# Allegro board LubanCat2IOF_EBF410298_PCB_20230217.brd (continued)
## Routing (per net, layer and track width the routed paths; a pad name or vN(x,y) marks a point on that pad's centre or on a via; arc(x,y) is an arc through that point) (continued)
I2C0_SDA: length 46.9
  TOP w0.173: v1(18.84,64.74) 19.14,64.44 41.15,64.44 41.6,63.98 J38.109
  ART03 w0.16: v1(18.84,64.74) 17.91,65.67 17.91,69.11 15.75,71.27 15.75,82.06 v1(14.1,83.71)
  BOTTOM w0.173: U17.5 v1(14.1,83.71)
I2C1_SCL: length 187.9
  TOP w0.173: J38.115 43.1,59.3 R35.2 42.8,58.33 42.8,38.58 v1(42.95,38.42) ; J23.9 155.8,68.43 156.14,68.08 156.14,53.13 155.75,52.74 v1(154.54,52.74) 154.05,52.24 154.05,49.35 156.21,47.19 156.21,36.45 155.78,36.01 146.94,36.01 v1(146.71,36.24)
  BOTTOM w0.173: v1(154.54,52.74) 154.12,52.74 153.07,53.78 J22.6 ; v1(42.95,38.42) 43.41,37.96 103.83,37.96 104.65,38.78 119.35,38.78 122.05,36.09 128.85,36.09 133.22,31.72 145.69,31.72 146.71,32.74 v1(146.71,36.24)
I2C1_SDA: length 195.5
  TOP w0.173: v1(42.44,37.64) 42.45,37.64 42.45,58.43 R33.2 42.6,59.66 J38.113 ; v1(145.71,36.24) 146.37,35.58 156.14,35.58 156.7,36.15 156.7,47.39 154.54,49.55 v1(154.54,51.74) 156.25,51.74 156.64,52.13 156.64,68.29 156,68.93 J23.10
  BOTTOM w0.173: v1(154.54,51.74) 153,53.28 J22.5 ; v1(145.71,36.24) 146.2,36.73 146.96,36.73 147.31,36.39 147.31,32.55 145.92,31.16 133.07,31.16 128.62,35.61 121.82,35.61 119.07,38.35 104.98,38.35 104.14,37.51 42.57,37.51 v1(42.44,37.64)
I2C5_SCL_M0: length 194
  TOP w0.173: v1(95.6,60.91) 95.6,60.9 95.07,60.37 94.27,60.37 94.1,60.54 J38.313 ; v1(153.85,46.22) 153.32,45.69 J26.9
  ART03 w0.16: v1(95.6,60.91) 96.13,60.37 109.7,60.37 112.27,57.81 112.27,43.71 114.55,41.42 114.55,25.75 113.72,24.91 113.72,23.24 113.03,22.55 113.03,16.29 112.71,15.97 107.19,15.97 106.95,15.73 J28.4 106.95,10.93 107.27,10.61 142.85,10.61 145.29,13.05 154.7,13.05 155.02,13.37 155.02,34.62 153.85,35.79 v1(153.85,46.22)
  BOTTOM w0.173: v1(153.85,46.22) 153.85,47.61 154.19,47.95 155.62,47.95 156.67,49 156.67,70.33 155.02,71.98 J24.6 ; R147.2 95.64,60.94 v1(95.6,60.91)
I2C5_SDA_M0: length 197.6
  TOP w0.173: J26.10 152.82,46.19 v1(152.85,46.22) ; J38.314 v1(94.6,60.91)
  ART03 w0.16: v1(94.6,60.91) 95.57,59.94 109.12,59.94 111.84,57.22 111.84,43.53 114.12,41.25 114.12,25.93 113.28,25.09 113.28,23.41 112.6,22.73 112.6,17.14 112.09,16.63 105.27,16.63 104.95,16.31 J28.5 104.95,10.5 105.27,10.18 143.03,10.18 145.47,12.62 155.11,12.62 155.55,13.06 155.55,34.84 154.38,36.01 154.38,46.37 154.05,46.7 153.33,46.7 v1(152.85,46.22)
  BOTTOM w0.173: v1(94.6,60.91) 94.48,61.03 R146.2 ; J24.5 154.75,71.48 156.29,69.95 156.29,49.16 155.46,48.33 153.16,48.33 152.85,48.02 v1(152.85,46.22)
LCD0_BL_PWM: length 102.2
  TOP w0.173: J38.187 v1(62.6,60.91) ; J23.13 v1(153.96,70.43)
  ART03 w0.16: v1(133.45,69.72) 133.94,70.21 147.79,70.21 148.18,69.82 153.36,69.82 v1(153.96,70.43)
  BOTTOM w0.173: v1(62.6,60.91) 63.11,60.4 65.33,60.4 74.17,69.24 96.88,69.24 99.47,66.64 103.37,66.64 104.5,67.76 114.2,67.76 115.06,68.63 132.35,68.63 v1(133.45,69.72)
LCD0_PWR_EN: length 109.7
  TOP w0.173: J38.235 74.6,60.41 v1(75.1,59.91) ; R195.1 v1(140.6,61.9)
  ART03 w0.16: v1(75.1,59.91) 75.61,60.42 77.27,60.42 78.3,59.39 90.72,59.39 92.25,57.86 107.04,57.86 108.28,56.61 108.28,45.77 107.65,45.13 107.65,41.39 v1(108.84,40.19)
  BOTTOM w0.173: v1(108.84,40.19) 108.88,40.15 132.89,40.15 134.85,42.11 138.11,42.11 138.46,42.45 138.46,45.54 138.81,45.89 141.69,45.89 142.04,46.24 142.04,60.46 v1(140.6,61.9)
LCD1_BL_PWM: length 118.4
  TOP w0.173: J38.185 62.1,58.41 v1(62.6,57.91) ; J26.13 v1(149.43,47.69)
  BOTTOM w0.173: v1(62.6,57.91) 63.19,58.49 65.89,58.49 73.41,66.01 92.79,66.01 94.62,67.84 96.24,67.84 98.48,65.6 102.49,65.6 103.1,64.99 118.34,64.99 120.52,67.17 141.99,67.17 142.52,66.65 142.52,48.7 142.86,48.36 148.77,48.36 v1(149.43,47.69)
LCD1_PWR_EN: length 87.5
  TOP w0.173: R200.2 139.83,39.04 139.6,39.26 134.75,39.26 v1(134.21,39.8) ; J38.237 v1(75.1,60.91)
  ART03 w0.16: v1(107.84,40.19) 106.98,41.05 106.98,45.64 107.67,46.33 107.67,56.25 106.56,57.36 92.22,57.36 90.58,59 77.83,59 77.43,59.39 74.93,59.39 74.91,59.42 74.9,59.42 74.61,59.7 74.61,60.42 v1(75.1,60.91)
  BOTTOM w0.173: v1(134.21,39.8) 134.06,39.65 108.39,39.65 v1(107.84,40.19)
LED_USR: length 111.2
  TOP w0.173: LED2.2 v1(139.07,98.39) ; v1(57.85,67.85) 58.35,68.35 J38.168
  BOTTOM w0.173: v1(57.85,67.85) 58.24,68.24 62.63,68.24 64.31,69.92 64.31,78.25 64.89,78.83 93.77,78.83 95.3,80.36 95.3,81.1 95.78,81.58 114.68,81.58 115.03,81.93 134.66,81.93 135,82.28 135,87.55 135.56,88.11 135.56,95.96 136.42,96.82 138.83,96.82 139.07,97.07 v1(139.07,98.39)
M2PCIE_3V3: length 53
  TOP w0.305: U21.1 v1(142.49,79.17) ; J17.14 139.9,83.6 v1(139.66,83.36) 139.4,83.62 J17.12 ; C69.2 R73.2 v1(135.13,57.59) ; v1(139.95,71.72) 140,71.67 R83.1 ; J17.18 140.9,83.6 v1(140.66,83.36) 140.4,83.62 J17.16 ; v1(139.45,80.82) 138.74,80.82 138.44,80.51 R86.1 R85.1 ; J17.4 137.4,83.6 v1(137.16,83.36) 136.9,83.62 J17.2 ; J17.70 153.9,85.87 v1(154.18,86.15) 154.4,85.93 J17.72
  TOP w0.381: v1(154.18,86.15) v1(154.18,87.15)
  ART04 w0.305: v1(135.13,57.59) 136.55,57.59 136.86,57.89 136.86,68.8
  BOTTOM w0.305: v1(139.95,71.72) 140,71.67 R83.1 ; R81.2 139.18,86.91 v1(138.94,87.15) ; v1(139.66,83.36) 139.44,83.14 C116.1 C115.1 142.16,78.15 142.49,78.48 v1(142.49,79.17) 145.61,79.17 146,78.79 R145.2 C136.1
  BOTTOM w0.381: v1(152.15,86.79) C130.1 C131.1 C129.1
  vias: v1(136.95,69.72) v1(137.95,69.72) v1(138.95,69.72) v1(138.95,68.72) v1(139.94,87.15) v1(152.15,85.79)
M2PCIE_PWR_EN: length 113.5
  TOP w0.173: v1(47.54,55.45) 47.6,55.51 J38.133 ; v1(126.11,52.5) v1(126.11,50.97)
  BOTTOM w0.173: v1(126.11,52.5) 132.29,52.5 132.64,52.84 132.64,61 132.87,61.24 136.13,61.24 R76.2 ; v1(47.54,55.45) 47.05,54.96 47.05,53.1 47.35,52.8 63.93,52.8 64.54,53.41 71.78,53.41 72.06,53.13 72.06,51.56 72.41,51.21 79.05,51.21 80.25,52.41 92.24,52.41 93.12,53.29 111.23,53.29 113.54,50.97 v1(126.11,50.97)
MDIN0_PHY0: length 36
  TOP w0.114: U18.2 68.71,51.65 68.79,51.73 68.79,52.03 69.18,52.42 69.18,52.55 v1(68.83,52.91)
  ART04 w0.102: v1(68.83,52.91) 69.27,53.35 69.27,76.75 73.91,81.39 73.91,82.8 73.76,82.95 72.95,82.95 72.84,82.85 J11.3
MDIN0_PHY1: length 35.3
  TOP w0.114: v1(89.4,52.91) 89.69,52.62 89.69,52.41 89.27,51.99 89.27,51.76 89.16,51.65 U19.2
  ART04 w0.102: v1(89.4,52.91) 89.58,53.08 89.58,53.09 89.72,53.23 89.72,78.66 92.23,81.16 92.23,82.93 92.1,83.05 91.23,83.05 91.1,82.93 J18.3
MDIN1_PHY0: length 43.3
  TOP w0.114: v1(67.68,53.93) 68.03,53.58 68.03,52.75 67.59,52.31 67.59,51.73 67.51,51.65 U18.5
  ART04 w0.102: v1(67.68,53.93) 68.02,54.27 68.02,77.49 71.31,80.77 71.31,82.78 70.18,83.9 70.18,85.85 69.98,86.05 67.97,86.05 67.76,85.85 J11.7
MDIN1_PHY1: length 43.1
  TOP w0.114: v1(88.11,53.93) 88.48,53.55 88.48,52.75 88.04,52.31 88.04,51.73 87.96,51.65 U19.5
  ART04 w0.102: v1(88.11,53.93) 88.42,54.24 88.42,79.66 89.69,80.93 89.69,83.28 89.48,83.49 88.71,83.49 88.34,83.85 88.34,85.96 88.2,86.1 86.18,86.1 86.02,85.94 J18.7
MDIN2_PHY0: length 34.9
  TOP w0.114: U18.7 66.71,51.65 66.79,51.73 66.79,52.58 v1(66.46,52.91)
  ART04 w0.102: J11.6 68.78,84.5 68.78,80.38 66.78,78.37 66.78,54.9 66.78,53.22 v1(66.46,52.91)
MDIN2_PHY1: length 34
  TOP w0.114: U19.7 87.16,51.65 87.24,51.73 87.24,52.58 v1(86.91,52.91)
  ART04 w0.102: v1(86.91,52.91) 87.22,53.22 87.22,54.9 87.22,84.68 J18.6
MDIN3_PHY0: length 34.3
  TOP w0.114: U18.10 65.51,51.65 65.59,51.73 65.59,53.62 v1(65.26,53.95)
  ART04 w0.102: J11.9 65.22,82.82 65.43,83.02 66.15,83.02 66.35,82.82 66.35,80.38 65.57,79.6 65.57,54.25 v1(65.26,53.95)
MDIN3_PHY1: length 34.7
  TOP w0.114: v1(85.71,53.95) 86.04,53.62 86.04,51.73 85.96,51.65 U19.10
  ART04 w0.102: v1(85.71,53.95) 86.02,54.25 86.02,79.83 84.66,81.19 84.66,82.88 84.48,83.05 83.66,83.05 83.48,82.88 J18.9
MDIP0_PHY0: length 36
  TOP w0.114: v1(69.72,52.91) 69.42,52.61 69.42,52.32 69.03,51.93 69.03,51.73 69.11,51.65 U18.1
  ART04 w0.102: J11.2 74.19,84.67 74.19,81.28 69.55,76.63 69.55,53.07 v1(69.72,52.91)
MDIP0_PHY1: length 35.2
  TOP w0.114: U19.1 89.56,51.65 89.52,51.69 89.52,51.89 89.93,52.31 89.93,52.54 v1(90.29,52.91)
  ART04 w0.102: v1(90.29,52.91) 90,53.2 90,78.54 92.51,81.05 92.51,84.62 J18.2
MDIP1_PHY0: length 43.4
  TOP w0.114: U18.4 67.91,51.65 67.83,51.73 67.83,52.21 68.28,52.65 68.28,53.63 v1(68.57,53.93)
  ART04 w0.102: J11.4 71.57,84.06 71.78,83.86 72.57,83.86 72.67,83.96 72.67,85.98 72.57,86.08 70.56,86.08 70.46,85.98 70.46,84.02 71.59,82.89 71.59,80.66 68.3,77.37 68.3,54.2 v1(68.57,53.93)
MDIP1_PHY1: length 43.2
  TOP w0.114: v1(89,53.93) 88.72,53.66 88.72,52.65 88.28,52.21 88.28,51.73 88.36,51.65 U19.4
  ART04 w0.102: J18.4 89.83,86.81 89.73,86.91 87.54,86.91 87.44,86.81 87.44,86.48 87.54,86.38 88.32,86.38 88.62,86.08 88.62,83.97 88.82,83.77 89.6,83.77 89.97,83.4 89.97,80.82 88.7,79.55 88.7,54.23 v1(89,53.93)
MDIP2_PHY0: length 34.8
  TOP w0.114: v1(67.36,52.91) 67.03,52.58 67.03,51.73 67.11,51.65 U18.6
  ART04 w0.102: J11.5 70.3,82.8 70.15,82.96 69.24,82.96 69.06,82.77 69.06,80.26 67.06,78.25 67.06,53.2 v1(67.36,52.91)
MDIP2_PHY1: length 34.1
  TOP w0.114: v1(87.8,52.91) 87.48,52.58 87.48,51.73 87.56,51.65 U19.6
  ART04 w0.102: J18.5 88.56,82.93 88.34,83.16 87.73,83.16 87.5,82.93 87.5,53.2 v1(87.8,52.91)
MDIP3_PHY0: length 34.4
  TOP w0.114: v1(66.16,53.95) 65.83,53.62 65.83,51.73 65.91,51.65 U18.9
  ART04 w0.102: v1(66.16,53.95) 65.85,54.25 65.85,79.49 66.63,80.27 66.63,84.61 J11.8
MDIP3_PHY1: length 34.6
  TOP w0.114: U19.9 86.36,51.65 86.28,51.73 86.28,53.62 v1(86.6,53.95)
  ART04 w0.102: J18.8 84.94,84.57 84.94,81.3 86.3,79.94 86.3,54.25 v1(86.6,53.95)
MIC1_INN: length 50.4
  TOP w0.114: v1(23.35,67.74) 22.85,68.24 J38.34
  BOTTOM w0.114: 44.2,78.6 J30.1 ; 44.2,78.6 43.98,78.38 43.98,76.59 44.2,76.37 ; 44.2,78.6 43.97,78.83 43.97,80.6 D30.1 44.02,81.75 44.03,81.76 44.03,83.03 44.25,83.24 45.78,83.24 46.15,83.61 46.15,88.35 J27.3 43.9,90.6 J27.4 ; 44.2,76.37 44.2,76.37 43.97,76.15 43.97,74.75 41.63,72.41 24.66,72.41 23.88,71.62 23.88,68.26 v1(23.35,67.74) ; 44.2,76.37 C217.2 R215.1
MIC1_INP: length 60.7
  TOP w0.114: J27.2 41.97,94.3 41.74,94.07 41.74,85.23 41.97,85 J27.1 ; J38.36 v1(23.35,68.74)
  BOTTOM w0.114: 43.5,78.6 J30.2 ; 43.5,78.6 43.74,78.36 43.74,76.61 43.5,76.37 43.5,76.37 ; 43.5,78.6 43.73,78.83 43.73,80.6 D29.1 43.79,81.86 43.79,83.13 44.15,83.49 45.68,83.49 45.91,83.71 45.91,86.03 45.68,86.25 44.03,86.25 43.8,86.03 J27.1 ; 43.5,76.37 C217.1 R214.2 ; 43.5,76.37 43.73,76.15 43.73,74.85 41.53,72.65 24.56,72.65 23.63,71.72 23.63,69.02 v1(23.35,68.74)
MINIPCIE_3V3: length 29.3
  TOP w0.305: J35.39 v1(110.3,75.31) ; v1(128.26,70.54) 128.3,70.5 J35.2 ; J35.24 v1(116.3,66.85) ; J35.52 v1(105.1,66.85) ; v1(132.13,59.59) 131.75,59.97 119.57,59.97 119.26,60.27 C32.1 R14.1 ; J35.41 v1(109.5,75.31)
  BOTTOM w0.305: v1(110.3,75.31) 110.24,75.36 C58.1 ; C55.1 105.16,66.78 v1(105.1,66.85) ; v1(116.3,66.85) 116.93,67.48 C56.1 ; R22.1 v1(128.26,70.54) 128.27,70.53 C57.1 ; v1(132.13,59.59) v1(132.13,61.73)
  vias: v1(132.13,64.73) v1(132.13,63.73) v1(132.13,62.73)
MINIPCIE_NWDISABLE: length 47.3
  TOP w0.173: R62.2 v1(117.98,63.83) ; J38.243 76.6,60.41 v1(77.1,59.91)
  BOTTOM w0.173: v1(77.1,59.91) 77.61,60.41 77.61,61.11 78.01,61.51 82.96,61.51 84.48,63.04 96.57,63.04 97.45,62.16 114.26,62.16 115.42,63.32 117.48,63.32 v1(117.98,63.83)
MINIPCIE_PWR_EN: length 85.5
  TOP w0.173: J38.245 v1(77.1,60.91)
  ART03 w0.16: v1(77.1,60.91) 77.24,60.91 78.36,59.79 90.98,59.79 92.44,58.33 107.43,58.33 108.74,57.02 108.74,45.06 v1(108.34,44.66)
  ART04 w0.16: v1(122.86,65.68) 122.86,61.41 122.22,60.78 122.22,51.65 121.9,51.33 119.78,51.33 119.46,51.01 119.46,45.27 120.03,44.7 v1(120.03,44.66)
  BOTTOM w0.173: R16.1 122.81,65.63 v1(122.86,65.68) ; v1(108.34,44.66) v1(120.03,44.66)
MIPI_CSI_RX_CLK0N: length 115.7
  TOP w0.114: J38.240 76.35,71.5 76.42,71.57 arc(76.46,71.64) 76.48,71.71 76.48,72.38 arc(76.44,72.59) 76.32,72.76 v1(76.15,72.93)
  ART03 w0.102: v1(155.52,55.74) 155.36,55.58 arc(155.2,55.48) 155.01,55.44 153.94,55.44 arc(153.85,55.48) 153.81,55.57 arc(153.78,55.66) 153.68,55.7 153.44,55.7 arc(153.34,55.66) 153.31,55.57 arc(153.27,55.48) 153.18,55.44 152.93,55.44 arc(152.84,55.48) 152.8,55.57 arc(152.76,55.66) 152.67,55.7 152.42,55.7 arc(152.33,55.66) 152.29,55.57 arc(152.25,55.48) 152.16,55.44 148.74,55.44 arc(147.95,55.77) 147.62,56.56 147.62,60 arc(147.59,60.19) 147.48,60.36 145.77,62.06 arc(144.69,62.78) 143.41,63.04 139.16,63.04 arc(138.31,63.21) 137.59,63.69 arc(136.57,64.37) 135.36,64.61 134.23,64.61 arc(133.77,64.71) 133.38,64.97 133.32,65.02 arc(132.62,65.49) 131.8,65.66 130.89,65.66 arc(129.88,65.86) 129.02,66.43 127.15,68.3 arc(126.56,68.69) 125.86,68.83 105.03,68.83 arc(104.19,68.66) 103.48,68.19 arc(103.45,68.15) 103.41,68.11 arc(102.54,67.57) 101.54,67.38 99.39,67.38 arc(99.25,67.44) 99.19,67.59 99.19,68.2 arc(99.01,68.63) 98.58,68.8 94.46,68.8 arc(94,68.61) 93.8,68.14 93.8,65.99 arc(93.68,65.7) 93.39,65.58 73.35,65.58 arc(73.05,65.64) 72.8,65.81 arc(72.63,66.06) 72.57,66.36 72.57,67.98 arc(72.61,68.09) 72.72,68.13 arc(72.83,68.17) 72.87,68.28 72.87,68.49 arc(72.83,68.59) 72.72,68.64 arc(72.61,68.68) 72.57,68.79 72.57,68.99 arc(72.61,69.1) 72.72,69.15 arc(72.83,69.19) 72.87,69.3 72.87,69.5 arc(72.83,69.61) 72.72,69.65 arc(72.61,69.7) 72.57,69.81 72.57,70.04 arc(72.61,70.14) 72.72,70.19 arc(72.83,70.23) 72.87,70.34 72.87,70.44 arc(72.83,70.55) 72.72,70.59 arc(72.61,70.64) 72.57,70.75 72.57,70.85 arc(72.61,70.96) 72.72,71 arc(72.83,71.04) 72.87,71.15 72.87,71.25 arc(72.83,71.36) 72.72,71.41 arc(72.61,71.45) 72.57,71.56 72.57,73.04 arc(72.77,73.52) 73.25,73.72 76.26,73.72 arc(76.4,73.66) 76.46,73.52 76.46,73.44 arc(76.42,73.25) 76.31,73.09 v1(76.15,72.93)
  BOTTOM w0.114: J22.10 152.15,55.78 arc(152.22,55.77) 152.29,55.72 152.3,55.71 arc(152.37,55.67) 152.44,55.65 153.66,55.65 arc(153.81,55.62) 153.93,55.54 154.01,55.46 arc(154.06,55.43) 154.11,55.42 154.98,55.42 arc(155.18,55.46) 155.35,55.57 v1(155.52,55.74)
MIPI_CSI_RX_CLK0P: length 115
  TOP w0.114: J38.242 76.85,71.42 arc(76.84,71.49) 76.79,71.56 76.78,71.57 arc(76.74,71.64) 76.72,71.71 76.72,72.38 arc(76.76,72.59) 76.87,72.76 v1(77.05,72.93)
  ART03 w0.102: v1(155.52,54.85) 155.36,55.01 arc(155.2,55.12) 155.01,55.16 148.74,55.16 arc(147.75,55.57) 147.35,56.56 147.35,60 arc(147.33,60.09) 147.28,60.16 145.58,61.86 arc(144.58,62.53) 143.41,62.76 139.16,62.76 arc(138.2,62.95) 137.39,63.49 arc(136.46,64.12) 135.36,64.33 134.23,64.33 arc(133.66,64.45) 133.18,64.77 133.12,64.83 arc(132.51,65.23) 131.8,65.38 130.89,65.38 arc(129.77,65.6) 128.82,66.23 126.96,68.1 arc(126.45,68.43) 125.86,68.55 105.03,68.55 arc(104.3,68.41) 103.68,67.99 103.6,67.91 103.6,67.91 arc(102.64,67.31) 101.54,67.1 99.39,67.1 arc(99.05,67.24) 98.91,67.59 98.91,68.2 arc(98.81,68.43) 98.58,68.53 94.46,68.53 arc(94.19,68.41) 94.08,68.14 94.08,65.99 arc(93.88,65.5) 93.39,65.3 73.35,65.3 arc(72.94,65.38) 72.6,65.61 arc(72.37,65.95) 72.29,66.36 72.29,73.04 arc(72.57,73.72) 73.25,74 76.26,74 arc(76.6,73.86) 76.74,73.52 76.74,73.44 arc(76.78,73.25) 76.89,73.09 v1(77.05,72.93)
  BOTTOM w0.114: J22.9 152.15,55.28 arc(152.22,55.3) 152.29,55.34 152.3,55.35 arc(152.37,55.4) 152.44,55.41 153.66,55.41 arc(153.71,55.4) 153.76,55.37 153.84,55.29 arc(153.96,55.21) 154.11,55.18 154.98,55.18 arc(155.18,55.14) 155.35,55.02 v1(155.52,54.85)
MIPI_CSI_RX_CLK1N: length 115.5
  TOP w0.114: v1(77.15,67.77) 77.41,68.03 arc(77.46,68.11) 77.48,68.19 77.48,69.02 arc(77.47,69.07) 77.44,69.11 77.41,69.13 arc(77.37,69.21) 77.35,69.29 J38.244
  ART03 w0.102: v1(77.15,67.77) 77.31,67.93 arc(77.42,68.09) 77.46,68.29 77.46,69.03 arc(77.4,69.18) 77.26,69.24 75.64,69.24 arc(75.3,69.38) 75.16,69.72 75.16,70.67 arc(75.34,71.11) 75.78,71.29 78.07,71.29 arc(78.45,71.14) 78.6,70.76 78.6,70.03 arc(78.86,69.77) 79.11,70.03 79.11,70.76 arc(79.27,71.14) 79.64,71.29 81.46,71.29 arc(81.6,71.35) 81.66,71.5 81.66,72.66 arc(82.14,73.14) 82.63,72.66 82.63,71.5 arc(82.69,71.35) 82.83,71.29 84.75,71.29 arc(84.97,71.39) 85.06,71.61 85.06,72.26 arc(85.21,72.6) 85.55,72.74 85.78,72.74 arc(86.12,72.6) 86.26,72.26 86.26,71.39 arc(86.46,71.18) 86.66,71.39 86.66,72.26 arc(86.81,72.6) 87.15,72.74 87.38,72.74 arc(87.72,72.6) 87.86,72.26 87.86,71.93 arc(88.06,71.73) 88.27,71.93 88.27,72.26 arc(88.41,72.6) 88.75,72.74 99.53,72.74 arc(100.36,72.91) 101.07,73.38 arc(101.6,73.73) 102.23,73.86 104.06,73.86 arc(104.21,73.92) 104.27,74.06 104.27,75.69 arc(104.41,76.03) 104.75,76.17 105.23,76.17 arc(105.57,76.03) 105.71,75.69 105.71,73.63 arc(105.91,73.43) 106.12,73.63 106.12,75.69 arc(106.26,76.03) 106.6,76.17 106.98,76.17 arc(107.33,76.03) 107.47,75.69 107.47,73.43 arc(107.53,73.28) 107.67,73.22 107.9,73.22 arc(108.04,73.28) 108.1,73.43 108.1,73.76 arc(108.29,74.21) 108.74,74.39 109.33,74.39 arc(109.41,74.43) 109.44,74.51 arc(109.47,74.59) 109.55,74.62 109.83,74.62 arc(109.91,74.59) 109.95,74.51 arc(109.98,74.43) 110.06,74.39 110.34,74.39 arc(110.42,74.43) 110.46,74.51 arc(110.51,74.64) 110.65,74.7 110.77,74.7 arc(110.91,74.64) 110.96,74.51 arc(111,74.43) 111.08,74.39 114.86,74.39 arc(115.2,74.25) 115.34,73.91 115.34,73.58 arc(115.42,73.4) 115.6,73.33 115.82,73.33 arc(116,73.4) 116.08,73.58 116.08,74.42 arc(116.61,74.95) 117.14,74.42 117.14,73.58 arc(117.22,73.4) 117.4,73.33 121.26,73.33 arc(121.48,73.42) 121.56,73.63 121.56,75.57 arc(121.61,75.81) 121.75,76.01 arc(121.97,76.16) 122.24,76.22 135.85,76.22 arc(136.03,76.18) 136.19,76.08 137.35,74.91 arc(137.42,74.87) 137.5,74.85 138.1,74.85 arc(138.48,74.69) 138.64,74.32 138.64,74.13 arc(138.69,74.01) 138.8,73.96 138.89,73.96 arc(139.07,74.04) 139.15,74.21 139.15,74.32 arc(139.3,74.69) 139.68,74.85 140.97,74.85 arc(141.31,74.71) 141.46,74.37 141.46,74.13 arc(141.5,74.01) 141.62,73.96 141.66,73.96 arc(141.8,74.02) 141.86,74.16 141.86,74.37 arc(142,74.71) 142.35,74.85 142.68,74.85 arc(142.86,74.81) 143.02,74.71 143.56,74.17 arc(143.62,74.12) 143.7,74.11 144.42,74.11 arc(144.61,74.14) 144.77,74.25 v1(144.93,74.41)
  BOTTOM w0.114: v1(144.93,74.41) 145.09,74.26 arc(145.25,74.15) 145.43,74.11 149.55,74.11 arc(149.72,74.08) 149.86,73.99 149.94,73.91 arc(150,73.87) 150.07,73.85 150.42,73.85 arc(150.49,73.87) 150.56,73.91 150.57,73.92 arc(150.63,73.97) 150.71,73.98 J24.10
MIPI_CSI_RX_CLK1P: length 114.8
  TOP w0.114: J38.246 77.85,69.29 arc(77.83,69.21) 77.79,69.13 77.76,69.11 arc(77.73,69.07) 77.72,69.02 77.72,68.19 arc(77.74,68.11) 77.79,68.03 v1(78.05,67.77)
  ART03 w0.102: v1(78.05,67.77) 77.89,67.93 arc(77.78,68.09) 77.74,68.29 77.74,69.03 arc(77.6,69.37) 77.26,69.52 75.64,69.52 arc(75.5,69.58) 75.44,69.72 75.44,70.67 arc(75.54,70.91) 75.78,71.01 76.44,71.01 arc(76.55,70.97) 76.59,70.86 arc(76.64,70.75) 76.74,70.71 76.84,70.71 arc(76.95,70.75) 77,70.86 arc(77.04,70.97) 77.15,71.01 78.07,71.01 arc(78.25,70.94) 78.32,70.76 78.32,70.03 arc(78.86,69.49) 79.39,70.03 79.39,70.76 arc(79.46,70.94) 79.64,71.01 81.46,71.01 arc(81.8,71.16) 81.94,71.5 81.94,72.66 arc(82.14,72.86) 82.35,72.66 82.35,71.5 arc(82.49,71.16) 82.83,71.01 84.75,71.01 arc(85.17,71.19) 85.34,71.61 85.34,72.26 arc(85.4,72.4) 85.55,72.46 85.78,72.46 arc(85.92,72.4) 85.98,72.26 85.98,71.39 arc(86.46,70.9) 86.94,71.39 86.94,72.26 arc(87,72.4) 87.15,72.46 87.38,72.46 arc(87.52,72.4) 87.58,72.26 87.58,71.93 arc(88.06,71.45) 88.54,71.93 88.54,72.26 arc(88.6,72.4) 88.75,72.46 99.53,72.46 arc(100.47,72.65) 101.26,73.18 arc(101.71,73.48) 102.23,73.58 104.06,73.58 arc(104.41,73.72) 104.55,74.06 104.55,75.69 arc(104.61,75.83) 104.75,75.89 105.23,75.89 arc(105.37,75.83) 105.43,75.69 105.43,73.63 arc(105.91,73.15) 106.4,73.63 106.4,75.69 arc(106.45,75.83) 106.6,75.89 106.98,75.89 arc(107.13,75.83) 107.19,75.69 107.19,73.43 arc(107.33,73.09) 107.67,72.94 107.9,72.94 arc(108.24,73.09) 108.38,73.43 108.38,73.76 arc(108.49,74.01) 108.74,74.11 114.86,74.11 arc(115,74.05) 115.06,73.91 115.06,73.58 arc(115.22,73.2) 115.6,73.05 115.82,73.05 arc(116.2,73.2) 116.36,73.58 116.36,74.42 arc(116.61,74.67) 116.87,74.42 116.87,73.58 arc(117.02,73.2) 117.4,73.05 121.26,73.05 arc(121.67,73.22) 121.84,73.63 121.84,75.57 arc(121.87,75.7) 121.95,75.82 arc(122.08,75.91) 122.24,75.94 135.85,75.94 arc(135.93,75.92) 135.99,75.88 137.16,74.71 arc(137.31,74.61) 137.5,74.57 138.1,74.57 arc(138.28,74.5) 138.36,74.32 138.36,74.13 arc(138.49,73.81) 138.8,73.68 138.89,73.68 arc(139.27,73.84) 139.42,74.21 139.42,74.32 arc(139.5,74.5) 139.68,74.57 140.97,74.57 arc(141.12,74.51) 141.18,74.37 141.18,74.13 arc(141.31,73.81) 141.62,73.68 141.66,73.68 arc(142,73.82) 142.14,74.16 142.14,74.37 arc(142.2,74.51) 142.35,74.57 142.68,74.57 arc(142.75,74.56) 142.82,74.51 143.36,73.97 arc(143.52,73.86) 143.7,73.83 144.42,73.83 arc(144.61,73.79) 144.77,73.68 v1(144.93,73.52)
  BOTTOM w0.114: J24.9 150.71,73.48 arc(150.63,73.5) 150.57,73.54 150.56,73.55 arc(150.49,73.6) 150.42,73.61 150.07,73.61 arc(149.91,73.64) 149.77,73.74 149.69,73.82 arc(149.63,73.86) 149.55,73.87 145.52,73.87 arc(145.3,73.83) 145.12,73.71 v1(144.93,73.52)
MIPI_CSI_RX_D0N: length 115.7
  TOP w0.114: J38.230 73.85,71.41 arc(73.87,71.49) 73.91,71.57 73.94,71.59 arc(73.97,71.63) 73.98,71.68 73.98,72.06 73.98,72.51 arc(73.96,72.59) 73.91,72.67 v1(73.65,72.93)
  ART03 w0.102: v1(73.65,72.93) 73.77,72.82 arc(73.84,72.71) 73.86,72.58 73.86,70.82 arc(73.83,70.73) 73.74,70.69 arc(73.65,70.65) 73.61,70.56 73.61,70.31 arc(73.65,70.22) 73.74,70.18 arc(73.83,70.14) 73.86,70.05 73.86,69.83 arc(73.81,69.71) 73.7,69.66 arc(73.58,69.61) 73.53,69.5 73.53,69.42 arc(73.58,69.3) 73.7,69.25 arc(73.81,69.21) 73.86,69.09 73.86,68.86 arc(73.83,68.78) 73.75,68.75 arc(73.67,68.71) 73.63,68.63 73.63,68.35 arc(73.67,68.27) 73.75,68.24 arc(73.83,68.2) 73.86,68.12 73.86,67.84 arc(73.83,67.76) 73.75,67.73 arc(73.67,67.7) 73.63,67.62 73.63,67.34 arc(73.67,67.26) 73.75,67.22 arc(73.83,67.19) 73.86,67.11 73.86,66.54 arc(74,66.2) 74.35,66.06 90.44,66.06 arc(90.89,66.25) 91.08,66.71 91.08,69.21 arc(91.14,69.35) 91.29,69.41 126.89,69.41 arc(126.97,69.4) 127.03,69.35 129.2,67.19 arc(129.35,67.09) 129.54,67.05 131.23,67.05 arc(132.72,66.76) 133.99,65.91 arc(134.52,65.55) 135.15,65.43 137.31,65.43 arc(138.27,65.24) 139.09,64.69 arc(139.71,64.28) 140.44,64.13 147.73,64.13 arc(147.94,64.09) 148.12,63.97 arc(148.24,63.79) 148.29,63.58 148.29,60.76 arc(148.32,60.6) 148.41,60.46 148.43,60.44 arc(148.56,60.35) 148.73,60.32 154.84,60.32 arc(155,60.29) 155.14,60.2 arc(155.23,60.06) 155.26,59.9 155.26,59.62 arc(155.15,59.35) 154.88,59.24 151.33,59.24 arc(150.85,58.76) 151.33,58.28 155.06,58.28 arc(155.2,58.22) 155.26,58.07 155.26,57.05 arc(155.25,56.97) 155.2,56.9 155.12,56.82 arc(155.05,56.77) 154.97,56.76 154.86,56.76 arc(154.78,56.78) 154.71,56.82 v1(154.46,57.06)
  BOTTOM w0.114: v1(154.46,57.06) 154.29,56.89 arc(154.12,56.78) 153.92,56.74 153.09,56.74 153,56.65 152.44,56.65 arc(152.37,56.67) 152.3,56.71 152.29,56.72 arc(152.22,56.77) 152.15,56.78 J22.12
MIPI_CSI_RX_D0P: length 115
  TOP w0.114: v1(74.55,72.93) 74.29,72.67 arc(74.24,72.59) 74.22,72.51 74.22,72.16 74.22,71.68 arc(74.23,71.63) 74.26,71.59 74.29,71.57 arc(74.33,71.49) 74.35,71.41 J38.232
  ART03 w0.102: v1(154.46,56.17) 154.64,56.34 arc(154.79,56.44) 154.96,56.48 154.97,56.48 arc(155.16,56.52) 155.32,56.62 155.4,56.7 arc(155.5,56.86) 155.54,57.05 155.54,58.07 arc(155.4,58.42) 155.06,58.56 151.33,58.56 arc(151.13,58.76) 151.33,58.96 154.88,58.96 arc(155.35,59.16) 155.54,59.62 155.54,59.9 arc(155.49,60.17) 155.34,60.4 arc(155.11,60.55) 154.84,60.6 148.73,60.6 arc(148.67,60.61) 148.62,60.64 148.61,60.66 arc(148.58,60.71) 148.56,60.76 148.56,63.58 arc(148.5,63.9) 148.32,64.17 arc(148.05,64.35) 147.73,64.41 140.44,64.41 arc(139.82,64.53) 139.29,64.89 arc(138.38,65.49) 137.31,65.71 135.15,65.71 arc(134.63,65.81) 134.18,66.11 arc(132.83,67.01) 131.23,67.33 129.54,67.33 arc(129.46,67.35) 129.39,67.39 127.23,69.55 arc(127.08,69.66) 126.89,69.69 91.29,69.69 arc(90.95,69.55) 90.81,69.21 90.81,66.71 arc(90.7,66.45) 90.44,66.34 74.35,66.34 arc(74.2,66.4) 74.14,66.54 74.14,72.31 arc(74.18,72.51) 74.29,72.67 v1(74.55,72.93)
  BOTTOM w0.114: J22.11 152.15,56.28 arc(152.22,56.3) 152.29,56.34 152.3,56.35 arc(152.37,56.4) 152.44,56.41 153.1,56.41 153.19,56.5 153.92,56.5 arc(154.12,56.46) 154.29,56.34 v1(154.46,56.17)
MIPI_CSI_RX_D1N: length 116.6
  TOP w0.114: v1(74.65,67.77) 74.91,68.03 arc(74.96,68.11) 74.98,68.19 74.98,69.02 arc(74.97,69.07) 74.94,69.11 74.91,69.13 arc(74.87,69.21) 74.85,69.29 J38.234
  ART03 w0.102: v1(154.54,54.63) 154.7,54.47 arc(154.87,54.36) 155.06,54.32 155.68,54.32 arc(155.77,54.34) 155.85,54.39 156.23,54.77 arc(156.27,54.83) 156.29,54.91 156.29,56.07 arc(156.25,56.15) 156.17,56.18 arc(156.09,56.22) 156.06,56.3 156.06,56.58 arc(156.09,56.66) 156.17,56.69 arc(156.25,56.72) 156.29,56.8 156.29,57.08 arc(156.25,57.17) 156.17,57.2 arc(156.09,57.23) 156.06,57.31 156.06,57.59 arc(156.09,57.67) 156.17,57.71 arc(156.25,57.74) 156.29,57.82 156.29,58.1 arc(156.25,58.18) 156.17,58.21 arc(156.09,58.25) 156.06,58.33 156.06,58.61 arc(156.09,58.69) 156.17,58.72 arc(156.25,58.76) 156.29,58.84 156.29,62.31 156.29,62.95 156.29,64.73 arc(156.22,64.9) 156.05,64.97 155.8,64.97 arc(155.6,64.89) 155.52,64.69 155.52,62.35 arc(155.04,61.87) 154.55,62.35 154.55,64.11 arc(154.35,64.31) 154.15,64.11 154.15,62.35 arc(153.66,61.87) 153.18,62.35 153.18,63 arc(153.12,63.15) 152.98,63.21 151.44,63.21 arc(151.23,63.25) 151.04,63.37 arc(150.92,63.56) 150.88,63.77 150.88,64.68 arc(150.85,64.8) 150.78,64.9 arc(150.68,64.97) 150.56,64.99 146.4,64.99 arc(146.2,65.03) 146.04,65.14 144.47,66.71 arc(144.4,66.76) 144.33,66.77 140.32,66.77 arc(140.12,66.81) 139.96,66.92 138.97,67.91 arc(138.91,67.95) 138.83,67.97 129.89,67.97 arc(129.71,68) 129.55,68.11 127.24,70.42 arc(127.17,70.47) 127.09,70.48 117.8,70.48 arc(117.3,70.58) 116.87,70.87 arc(116.54,71.09) 116.15,71.17 109.05,71.17 arc(108.39,71.03) 107.82,70.66 arc(107.37,70.36) 106.84,70.25 90.15,70.25 arc(89.99,70.22) 89.86,70.13 89.75,70.02 arc(89.7,69.95) 89.69,69.88 89.69,69.63 arc(89.72,69.56) 89.79,69.53 arc(89.86,69.5) 89.89,69.42 89.89,69.22 arc(89.86,69.15) 89.79,69.12 arc(89.72,69.09) 89.69,69.02 89.69,68.81 arc(89.72,68.74) 89.79,68.71 arc(89.86,68.68) 89.89,68.61 89.89,68.41 arc(89.86,68.34) 89.79,68.31 arc(89.72,68.28) 89.69,68.21 89.69,67.53 arc(89.64,67.3) 89.51,67.1 arc(89.23,66.92) 88.9,66.85 75.43,66.85 arc(75.1,66.99) 74.96,67.32 74.96,67.43 arc(74.95,67.46) 74.93,67.5 v1(74.65,67.77)
  BOTTOM w0.114: J22.8 152.15,54.78 arc(152.22,54.77) 152.29,54.72 152.3,54.71 arc(152.37,54.67) 152.44,54.65 153.03,54.65 arc(153.3,54.6) 153.53,54.45 arc(153.69,54.34) 153.87,54.3 154,54.3 arc(154.2,54.34) 154.37,54.46 v1(154.54,54.63)
MIPI_CSI_RX_D1P: length 115.8
  TOP w0.114: v1(75.55,67.77) 75.29,68.03 arc(75.24,68.11) 75.22,68.19 75.22,69.02 arc(75.23,69.07) 75.26,69.11 75.29,69.13 arc(75.33,69.21) 75.35,69.29 J38.236
  ART03 w0.102: v1(154.54,53.74) 154.7,53.9 arc(154.87,54) 155.06,54.04 155.68,54.04 arc(155.88,54.08) 156.04,54.19 156.42,54.57 arc(156.53,54.73) 156.57,54.91 156.57,62.31 156.57,62.95 156.57,64.73 arc(156.41,65.1) 156.05,65.25 155.8,65.25 arc(155.4,65.08) 155.24,64.69 155.24,62.35 arc(155.04,62.15) 154.83,62.35 154.83,64.11 arc(154.35,64.59) 153.87,64.11 153.87,62.35 arc(153.66,62.15) 153.46,62.35 153.46,63 arc(153.32,63.34) 152.98,63.49 151.44,63.49 arc(151.33,63.51) 151.24,63.57 arc(151.18,63.66) 151.16,63.77 151.16,64.68 arc(151.11,64.91) 150.98,65.1 arc(150.79,65.23) 150.56,65.27 146.4,65.27 arc(146.31,65.29) 146.24,65.34 144.67,66.91 arc(144.51,67.02) 144.33,67.05 140.32,67.05 arc(140.23,67.07) 140.16,67.12 139.17,68.1 arc(139.01,68.21) 138.83,68.25 129.89,68.25 arc(129.81,68.26) 129.75,68.31 127.43,70.62 arc(127.28,70.72) 127.09,70.76 117.8,70.76 arc(117.41,70.84) 117.07,71.07 arc(116.65,71.35) 116.15,71.45 109.05,71.45 arc(108.28,71.29) 107.63,70.86 arc(107.27,70.62) 106.84,70.53 90.15,70.53 arc(89.89,70.48) 89.66,70.33 89.55,70.22 arc(89.44,70.06) 89.41,69.88 89.41,67.53 arc(89.38,67.41) 89.31,67.3 arc(89.12,67.17) 88.9,67.13 75.43,67.13 arc(75.3,67.19) 75.24,67.32 75.24,67.43 arc(75.25,67.46) 75.27,67.5 v1(75.55,67.77)
  BOTTOM w0.114: J22.7 152.15,54.28 arc(152.22,54.3) 152.29,54.34 152.3,54.35 arc(152.37,54.4) 152.44,54.41 153.03,54.41 arc(153.21,54.38) 153.36,54.27 arc(153.59,54.12) 153.87,54.06 154.13,54.06 arc(154.21,54.04) 154.28,53.99 v1(154.54,53.74)
MIPI_CSI_RX_D2N: length 107.6
  TOP w0.114: J38.250 78.85,71.41 arc(78.87,71.49) 78.91,71.57 78.94,71.59 arc(78.97,71.63) 78.98,71.68 78.98,72.26 78.98,72.51 arc(78.96,72.59) 78.91,72.67 v1(78.65,72.93) ; v1(146.05,75.68) 145.88,75.51 arc(145.71,75.39) 145.51,75.35 144.59,75.35 arc(144.47,75.38) 144.36,75.45 144.29,75.52 arc(144.22,75.62) 144.2,75.75 144.2,76.11 arc(144.24,76.31) 144.35,76.48 v1(144.52,76.65)
  ART03 w0.102: v1(78.65,72.93) 78.81,73.09 arc(78.92,73.25) 78.96,73.44 78.96,73.76 arc(79.07,74.03) 79.34,74.14 81.53,74.14 arc(81.62,74.18) 81.67,74.28 arc(81.71,74.38) 81.81,74.42 81.93,74.42 arc(82.03,74.38) 82.07,74.28 arc(82.11,74.18) 82.21,74.14 85.38,74.14 arc(85.57,74.1) 85.74,73.99 86.15,73.57 arc(86.23,73.52) 86.32,73.5 98.29,73.5 arc(98.38,73.52) 98.45,73.57 99.46,74.57 arc(99.62,74.68) 99.82,74.72 101.62,74.72 arc(101.71,74.74) 101.78,74.79 103.78,76.79 arc(103.95,76.9) 104.14,76.94 118.37,76.94 arc(118.72,76.8) 118.86,76.46 118.86,74.65 arc(119.06,74.44) 119.26,74.65 119.26,76.46 arc(119.75,76.94) 120.23,76.46 120.23,74.65 arc(120.43,74.44) 120.63,74.65 120.63,76.46 arc(120.78,76.8) 121.12,76.94 136.34,76.94 arc(136.53,76.91) 136.68,76.8 137.51,75.98 arc(137.57,75.93) 137.65,75.92 144.76,75.92 arc(144.94,75.88) 145.1,75.78 145.47,75.41 arc(145.51,75.38) 145.56,75.37 145.64,75.37 arc(145.74,75.39) 145.83,75.45 v1(146.05,75.68)
  BOTTOM w0.114: R233.1 147,75.74 arc(146.92,75.71) 146.89,75.62 146.89,75.47 arc(146.86,75.39) 146.78,75.35 146.57,75.35 arc(146.39,75.39) 146.25,75.48 v1(146.05,75.68) ; R227.1 146.98,59.54 arc(146.9,59.51) 146.87,59.42 146.87,59.27 arc(146.83,59.19) 146.75,59.15 145.86,59.15 arc(145.73,59.18) 145.62,59.25 145.23,59.64 arc(145.16,59.75) 145.14,59.87 145.14,70.19 arc(145.09,70.41) 144.97,70.6 144.29,71.27 arc(144.22,71.38) 144.2,71.51 144.2,76.11 arc(144.24,76.31) 144.35,76.48 v1(144.52,76.65)
MIPI_CSI_RX_D2P: length 107.6
  TOP w0.114: v1(79.55,72.93) 79.29,72.67 arc(79.24,72.59) 79.22,72.51 79.22,72.16 79.22,71.68 arc(79.23,71.63) 79.26,71.59 79.29,71.57 arc(79.33,71.49) 79.35,71.41 J38.252 ; v1(146.05,74.79) 145.88,74.96 arc(145.71,75.07) 145.51,75.11 144.59,75.11 arc(144.37,75.15) 144.19,75.28 144.12,75.34 arc(144,75.53) 143.95,75.75 143.95,76.11 arc(143.91,76.31) 143.8,76.48 v1(143.63,76.65)
  ART03 w0.102: v1(79.55,72.93) 79.39,73.09 arc(79.28,73.25) 79.24,73.44 79.24,73.76 arc(79.27,73.83) 79.34,73.86 85.38,73.86 arc(85.46,73.84) 85.54,73.79 85.96,73.37 arc(86.12,73.26) 86.32,73.22 98.29,73.22 arc(98.49,73.26) 98.65,73.37 99.65,74.38 arc(99.73,74.43) 99.82,74.44 101.62,74.44 arc(101.81,74.48) 101.98,74.59 103.98,76.6 arc(104.06,76.65) 104.14,76.66 118.37,76.66 arc(118.52,76.6) 118.58,76.46 118.58,74.65 arc(119.06,74.16) 119.54,74.65 119.54,76.46 arc(119.75,76.66) 119.95,76.46 119.95,74.65 arc(120.43,74.16) 120.91,74.65 120.91,76.46 arc(120.97,76.6) 121.12,76.66 136.34,76.66 arc(136.42,76.65) 136.48,76.6 137.31,75.78 arc(137.47,75.67) 137.65,75.64 144.76,75.64 arc(144.84,75.62) 144.9,75.58 145.27,75.21 arc(145.4,75.12) 145.56,75.09 145.58,75.09 arc(145.74,75.06) 145.87,74.97 v1(146.05,74.79)
  BOTTOM w0.114: R232.1 147,74.72 arc(146.92,74.76) 146.89,74.84 146.89,75 arc(146.86,75.08) 146.78,75.11 146.57,75.11 arc(146.39,75.08) 146.25,74.98 v1(146.05,74.79) ; R226.1 146.98,58.52 arc(146.9,58.56) 146.87,58.64 146.87,58.8 arc(146.83,58.88) 146.75,58.91 145.86,58.91 arc(145.64,58.95) 145.45,59.08 145.06,59.47 arc(144.94,59.65) 144.89,59.87 144.89,70.19 arc(144.87,70.32) 144.8,70.43 144.12,71.1 arc(144,71.29) 143.95,71.51 143.95,76.11 arc(143.91,76.31) 143.8,76.48 v1(143.63,76.65)
MIPI_CSI_RX_D3N: length 100.2
  TOP w0.114: J38.254 79.85,69.29 arc(79.87,69.21) 79.91,69.13 79.94,69.11 arc(79.97,69.07) 79.98,69.02 79.98,68.19 arc(79.96,68.11) 79.91,68.03 v1(79.65,67.77)
  ART03 w0.102: v1(146.05,73.18) 145.89,73.02 arc(145.73,72.91) 145.54,72.87 136.72,72.87 arc(136.53,72.91) 136.36,73.02 arc(136.22,73.23) 136.17,73.48 136.17,73.96 arc(136.01,74.36) 135.61,74.52 131.21,74.52 arc(131.07,74.58) 131.01,74.72 131.01,74.9 arc(130.9,75.17) 130.63,75.28 130.52,75.28 arc(130.18,75.14) 130.04,74.8 130.04,74.72 arc(129.98,74.58) 129.84,74.52 129.61,74.52 arc(129.47,74.58) 129.41,74.72 129.41,74.85 arc(128.92,75.33) 128.44,74.85 128.44,74.65 arc(128.4,74.56) 128.31,74.52 128.24,74.52 arc(128.09,74.58) 128.03,74.72 128.03,74.85 arc(127.55,75.33) 127.07,74.85 127.07,74.55 arc(127.03,74.46) 126.94,74.42 126.87,74.42 arc(126.72,74.48) 126.66,74.62 126.66,74.85 arc(126.52,75.19) 126.18,75.33 125.09,75.33 arc(124.65,75.15) 124.46,74.7 124.46,72.59 arc(124.39,72.43) 124.24,72.36 108.62,72.36 arc(107.75,72.19) 107.02,71.69 arc(106.6,71.42) 106.11,71.32 90.02,71.32 arc(89.18,71.15) 88.47,70.68 arc(88.23,70.51) 87.94,70.46 86.28,70.46 arc(85.94,70.31) 85.8,69.97 85.8,68.07 arc(85.6,67.86) 85.39,68.07 85.39,69.97 arc(85.25,70.31) 84.91,70.46 82.74,70.46 arc(82.39,70.31) 82.25,69.97 82.25,68.93 arc(82.05,68.73) 81.85,68.93 81.85,69.97 arc(81.71,70.31) 81.36,70.46 80.48,70.46 arc(80.3,70.42) 80.14,70.31 80.1,70.27 arc(80,70.12) 79.96,69.93 79.96,68.29 arc(79.92,68.09) 79.81,67.93 v1(79.65,67.77)
  BOTTOM w0.114: R231.1 147,73.24 arc(146.92,73.21) 146.89,73.12 146.89,72.97 arc(146.86,72.89) 146.78,72.85 146.57,72.85 arc(146.39,72.89) 146.25,72.98 v1(146.05,73.18) 145.88,73.01 arc(145.71,72.89) 145.51,72.85 145.41,72.85 arc(145.12,72.73) 145,72.44 145,71.99 arc(145.04,71.77) 145.16,71.59 145.84,70.91 arc(145.91,70.8) 145.94,70.68 145.94,64.88 arc(146.04,64.63) 146.29,64.53 146.75,64.53 arc(146.83,64.49) 146.87,64.41 146.87,64.25 arc(146.9,64.17) 146.98,64.14 R229.1
MIPI_CSI_RX_D3P: length 99.3
  TOP w0.114: v1(80.55,67.77) 80.29,68.03 arc(80.24,68.11) 80.22,68.19 80.22,69.02 arc(80.23,69.07) 80.26,69.11 80.29,69.13 arc(80.33,69.21) 80.35,69.29 J38.256
  ART03 w0.102: v1(80.55,67.77) 80.39,67.93 arc(80.28,68.09) 80.24,68.29 80.24,69.93 arc(80.25,70.01) 80.3,70.07 80.34,70.12 arc(80.41,70.16) 80.48,70.18 81.36,70.18 arc(81.51,70.12) 81.57,69.97 81.57,68.93 arc(82.05,68.45) 82.53,68.93 82.53,69.97 arc(82.59,70.12) 82.74,70.18 84.91,70.18 arc(85.06,70.12) 85.11,69.97 85.11,68.07 arc(85.6,67.59) 86.08,68.07 86.08,69.97 arc(86.14,70.12) 86.28,70.18 86.68,70.18 arc(86.77,70.14) 86.8,70.05 arc(86.86,69.92) 86.98,69.87 87.03,69.87 arc(87.16,69.92) 87.21,70.05 arc(87.25,70.14) 87.34,70.18 87.94,70.18 arc(88.33,70.26) 88.67,70.48 arc(89.29,70.89) 90.02,71.04 106.11,71.04 arc(106.71,71.16) 107.21,71.5 arc(107.86,71.93) 108.62,72.08 124.24,72.08 arc(124.59,72.23) 124.74,72.59 124.74,74.7 arc(124.84,74.95) 125.09,75.05 126.18,75.05 arc(126.32,74.99) 126.38,74.85 126.38,74.62 arc(126.53,74.28) 126.87,74.14 126.94,74.14 arc(127.23,74.26) 127.35,74.55 127.35,74.85 arc(127.55,75.05) 127.76,74.85 127.76,74.72 arc(127.9,74.38) 128.24,74.24 128.31,74.24 arc(128.6,74.36) 128.72,74.65 128.72,74.85 arc(128.92,75.05) 129.13,74.85 129.13,74.72 arc(129.27,74.38) 129.61,74.24 129.84,74.24 arc(130.18,74.38) 130.32,74.72 130.32,74.8 arc(130.38,74.94) 130.52,75 130.63,75 arc(130.7,74.97) 130.73,74.9 130.73,74.72 arc(130.87,74.38) 131.21,74.24 135.61,74.24 arc(135.81,74.16) 135.89,73.96 135.89,73.48 arc(135.96,73.12) 136.16,72.82 arc(136.42,72.65) 136.72,72.59 145.54,72.59 arc(145.73,72.55) 145.89,72.45 v1(146.05,72.29)
  BOTTOM w0.114: R230.1 147,72.22 arc(146.92,72.26) 146.89,72.34 146.89,72.5 arc(146.86,72.58) 146.78,72.61 146.57,72.61 arc(146.39,72.58) 146.25,72.48 v1(146.05,72.29) 145.88,72.46 arc(145.71,72.57) 145.51,72.61 145.41,72.61 arc(145.29,72.56) 145.24,72.44 145.24,71.99 arc(145.26,71.86) 145.33,71.76 146.01,71.08 arc(146.13,70.89) 146.18,70.68 146.18,64.88 arc(146.21,64.8) 146.29,64.77 146.75,64.77 arc(146.83,64.8) 146.87,64.88 146.87,65.04 arc(146.9,65.12) 146.98,65.15 R228.1
MIPI_DSI_TX0_CLKN: length 111.7
  TOP w0.114: v1(155.73,76.12) 155.56,75.95 arc(155.39,75.84) 155.18,75.8 152.49,75.8 arc(152.42,75.81) 152.35,75.85 152.28,75.93 J23.24 ; J38.216 70.35,71.5 70.48,71.63 70.48,76.9 arc(70.55,77.28) 70.77,77.59 arc(71.08,77.8) 71.44,77.87 96.32,77.87 v1(96.65,78.2)
  ART03 w0.102: v1(96.65,78.2) 96.81,78.04 arc(96.97,77.93) 97.16,77.89 97.54,77.89 arc(97.68,77.95) 97.74,78.09 97.74,79.34 arc(97.8,79.65) 97.98,79.91 98.19,80.12 arc(98.37,80.24) 98.58,80.29 99.08,80.29 arc(99.22,80.35) 99.28,80.49 arc(99.4,80.78) 99.68,80.9 99.84,80.9 arc(100.12,80.78) 100.24,80.49 arc(100.45,80.29) 100.65,80.49 arc(100.77,80.78) 101.06,80.9 101.21,80.9 arc(101.5,80.78) 101.62,80.49 arc(101.82,80.29) 102.02,80.49 arc(102.14,80.78) 102.43,80.9 102.58,80.9 arc(102.87,80.78) 102.99,80.49 arc(103.19,80.29) 103.39,80.49 arc(103.51,80.78) 103.8,80.9 103.95,80.9 arc(104.24,80.78) 104.36,80.49 arc(104.56,80.29) 104.76,80.49 arc(104.88,80.78) 105.17,80.9 105.32,80.9 arc(105.61,80.78) 105.73,80.49 105.73,80.36 arc(105.93,80.16) 106.14,80.36 106.14,80.49 arc(106.26,80.78) 106.54,80.9 106.7,80.9 arc(106.98,80.78) 107.1,80.49 107.1,80.34 arc(107.3,80.13) 107.51,80.34 107.51,80.49 arc(107.63,80.78) 107.91,80.9 108.07,80.9 arc(108.35,80.78) 108.47,80.49 arc(108.57,80.26) 108.79,80.17 arc(109.06,80.28) 109.17,80.55 109.17,81.01 arc(109.36,81.47) 109.82,81.66 119.59,81.66 arc(119.66,81.67) 119.73,81.72 119.83,81.81 arc(119.99,81.92) 120.19,81.96 138.05,81.96 arc(138.23,82.04) 138.31,82.22 138.31,82.36 arc(138.42,82.63) 138.7,82.75 138.84,82.75 arc(139.22,82.59) 139.38,82.22 arc(139.45,82.04) 139.63,81.96 148.14,81.96 arc(148.33,81.92) 148.5,81.81 148.57,81.74 arc(148.68,81.58) 148.72,81.38 148.72,79.75 arc(148.73,79.67) 148.78,79.61 149.61,78.77 arc(149.72,78.61) 149.76,78.41 149.76,76.15 arc(149.78,76.07) 149.83,75.99 149.93,75.88 arc(150.01,75.83) 150.1,75.81 155.22,75.81 arc(155.41,75.85) 155.57,75.96 v1(155.73,76.12)
MIPI_DSI_TX0_CLKP: length 111.9
  TOP w0.114: J38.218 70.85,71.42 arc(70.84,71.49) 70.79,71.56 70.78,71.57 arc(70.74,71.64) 70.72,71.71 70.72,72.17 arc(70.75,72.23) 70.81,72.26 arc(70.87,72.28) 70.89,72.34 70.89,72.63 arc(70.87,72.69) 70.81,72.71 arc(70.75,72.74) 70.72,72.8 70.72,73.08 arc(70.75,73.14) 70.81,73.17 arc(70.87,73.19) 70.89,73.26 70.89,73.54 arc(70.87,73.6) 70.81,73.63 arc(70.75,73.65) 70.72,73.71 70.72,73.95 arc(70.75,74.02) 70.82,74.05 arc(70.89,74.08) 70.92,74.15 70.92,74.53 arc(70.89,74.59) 70.82,74.62 arc(70.75,74.65) 70.72,74.72 70.72,76.9 arc(70.78,77.18) 70.94,77.42 arc(71.17,77.58) 71.44,77.63 96.32,77.63 v1(96.65,77.31) ; J23.23 152.28,75.43 152.35,75.5 arc(152.42,75.54) 152.49,75.55 155.18,75.55 arc(155.39,75.51) 155.56,75.4 v1(155.73,75.23)
  ART03 w0.102: v1(155.73,75.23) 155.57,75.39 arc(155.41,75.5) 155.22,75.54 150.1,75.54 arc(149.9,75.57) 149.74,75.68 149.63,75.79 arc(149.52,75.96) 149.48,76.15 149.48,78.41 arc(149.46,78.5) 149.41,78.57 148.58,79.41 arc(148.47,79.56) 148.44,79.75 148.44,81.38 arc(148.42,81.47) 148.37,81.55 148.3,81.62 arc(148.23,81.67) 148.14,81.68 139.63,81.68 arc(139.25,81.84) 139.1,82.22 arc(139.02,82.4) 138.84,82.47 138.7,82.47 arc(138.62,82.44) 138.59,82.36 138.59,82.22 arc(138.43,81.84) 138.05,81.68 120.19,81.68 arc(120.1,81.67) 120.02,81.62 119.93,81.52 arc(119.77,81.41) 119.59,81.38 109.82,81.38 arc(109.56,81.27) 109.45,81.01 109.45,80.55 arc(109.26,80.08) 108.79,79.89 arc(108.37,80.07) 108.19,80.49 arc(108.16,80.58) 108.07,80.62 107.91,80.62 arc(107.82,80.58) 107.79,80.49 107.79,80.34 arc(107.3,79.85) 106.82,80.34 106.82,80.49 arc(106.79,80.58) 106.7,80.62 106.54,80.62 arc(106.45,80.58) 106.42,80.49 106.42,80.36 arc(105.93,79.88) 105.45,80.36 105.45,80.49 arc(105.41,80.58) 105.32,80.62 105.17,80.62 arc(105.08,80.58) 105.04,80.49 arc(104.56,80.01) 104.08,80.49 arc(104.04,80.58) 103.95,80.62 103.8,80.62 arc(103.71,80.58) 103.67,80.49 arc(103.19,80.01) 102.71,80.49 arc(102.67,80.58) 102.58,80.62 102.43,80.62 arc(102.34,80.58) 102.3,80.49 arc(101.82,80.01) 101.34,80.49 arc(101.3,80.58) 101.21,80.62 101.06,80.62 arc(100.97,80.58) 100.93,80.49 arc(100.45,80.01) 99.96,80.49 arc(99.93,80.58) 99.84,80.62 99.68,80.62 arc(99.6,80.58) 99.56,80.49 arc(99.42,80.15) 99.08,80.01 98.58,80.01 arc(98.47,79.99) 98.38,79.93 98.18,79.72 arc(98.06,79.54) 98.02,79.34 98.02,78.09 arc(97.88,77.75) 97.54,77.61 97.16,77.61 arc(96.97,77.57) 96.81,77.47 v1(96.65,77.31)
MIPI_DSI_TX0_D0N: length 111.6
  TOP w0.114: J38.206 67.85,71.5 67.98,71.63 67.98,78.96 arc(68.38,79.93) 69.35,80.34 96.46,80.34 v1(96.7,80.57) ; v1(153.57,77.62) 153.4,77.45 arc(153.23,77.34) 153.03,77.3 152.49,77.3 arc(152.42,77.31) 152.35,77.35 152.28,77.43 J23.27
  ART03 w0.102: v1(153.57,77.62) 153.41,77.46 arc(153.25,77.35) 153.06,77.31 151.67,77.31 arc(151.47,77.35) 151.31,77.47 arc(151.19,77.63) 151.16,77.83 151.16,83.46 arc(151.1,83.74) 150.94,83.98 arc(150.7,84.14) 150.42,84.2 150.12,84.2 arc(149.71,84.03) 149.53,83.61 149.53,83.16 arc(149.33,82.95) 149.13,83.16 149.13,83.71 arc(148.64,84.2) 148.16,83.71 148.16,83.16 arc(147.96,82.95) 147.76,83.16 147.76,83.71 arc(147.61,84.06) 147.27,84.2 136.1,84.2 arc(135.92,84.16) 135.76,84.06 135.56,83.86 arc(135.49,83.81) 135.4,83.79 126.52,83.79 arc(126.18,83.65) 126.03,83.31 126.03,83.05 arc(125.98,82.93) 125.86,82.88 125.83,82.88 arc(125.69,82.94) 125.63,83.08 125.63,83.31 arc(125.49,83.65) 125.15,83.79 123.64,83.79 arc(123.3,83.65) 123.16,83.31 123.16,83.08 arc(123.1,82.94) 122.96,82.88 122.93,82.88 arc(122.81,82.93) 122.75,83.05 122.75,83.31 arc(122.61,83.65) 122.27,83.79 117.88,83.79 arc(117.56,83.73) 117.3,83.55 116.16,82.41 arc(116.08,82.36) 115.99,82.34 108.26,82.34 arc(107.83,82.26) 107.47,82.02 107.31,81.86 arc(107.03,81.67) 106.7,81.61 99.26,81.61 arc(98.64,81.48) 98.12,81.13 97.31,80.33 arc(97.25,80.29) 97.18,80.27 arc(97.17,80.27) 97.17,80.27 arc(97.02,80.3) 96.89,80.38 v1(96.7,80.57)
MIPI_DSI_TX0_D0P: length 112.3
  TOP w0.114: J23.26 152.28,76.93 152.35,77 arc(152.42,77.04) 152.49,77.05 153.03,77.05 arc(153.23,77.01) 153.4,76.9 v1(153.57,76.73) ; v1(96.7,79.68) 96.29,80.1 69.35,80.1 arc(68.55,79.76) 68.22,78.96 68.22,76.22 arc(68.26,76.12) 68.35,76.09 arc(68.44,76.05) 68.48,75.96 68.48,75.64 arc(68.44,75.55) 68.35,75.52 arc(68.26,75.48) 68.22,75.39 68.22,75.07 arc(68.26,74.98) 68.35,74.94 arc(68.44,74.91) 68.48,74.81 68.48,74.5 arc(68.44,74.41) 68.35,74.37 arc(68.26,74.33) 68.22,74.24 68.22,73.88 arc(68.25,73.81) 68.31,73.79 arc(68.38,73.76) 68.4,73.69 68.4,73.42 arc(68.38,73.35) 68.31,73.33 arc(68.25,73.3) 68.22,73.24 68.22,72.96 arc(68.25,72.9) 68.31,72.87 arc(68.38,72.84) 68.4,72.78 68.4,72.5 arc(68.38,72.44) 68.31,72.41 arc(68.25,72.39) 68.22,72.32 68.22,71.71 arc(68.24,71.64) 68.28,71.57 68.29,71.56 arc(68.34,71.49) 68.35,71.42 J38.208
  ART03 w0.102: v1(96.7,79.68) 96.86,79.84 arc(97.01,79.95) 97.19,79.99 arc(97.19,79.99) 97.19,79.99 arc(97.36,80.03) 97.51,80.13 98.31,80.94 arc(98.75,81.23) 99.26,81.33 106.7,81.33 arc(107.14,81.41) 107.51,81.66 107.67,81.82 arc(107.94,82) 108.26,82.06 115.99,82.06 arc(116.19,82.1) 116.35,82.21 117.49,83.35 arc(117.67,83.47) 117.88,83.51 122.27,83.51 arc(122.42,83.45) 122.47,83.31 122.47,83.05 arc(122.61,82.73) 122.93,82.6 122.96,82.6 arc(123.3,82.74) 123.44,83.08 123.44,83.31 arc(123.5,83.45) 123.64,83.51 125.15,83.51 arc(125.29,83.45) 125.35,83.31 125.35,83.08 arc(125.49,82.74) 125.83,82.6 125.86,82.6 arc(126.18,82.73) 126.31,83.05 126.31,83.31 arc(126.37,83.45) 126.52,83.51 135.4,83.51 arc(135.59,83.55) 135.76,83.66 135.96,83.86 arc(136.02,83.9) 136.1,83.92 147.27,83.92 arc(147.42,83.86) 147.48,83.71 147.48,83.16 arc(147.96,82.67) 148.44,83.16 148.44,83.71 arc(148.64,83.92) 148.85,83.71 148.85,83.16 arc(149.33,82.67) 149.81,83.16 149.81,83.61 arc(149.9,83.83) 150.12,83.92 150.42,83.92 arc(150.6,83.88) 150.74,83.78 arc(150.84,83.64) 150.88,83.46 150.88,77.83 arc(150.94,77.53) 151.11,77.27 arc(151.37,77.1) 151.67,77.04 153.06,77.04 arc(153.25,77) 153.41,76.89 v1(153.57,76.73)
MIPI_DSI_TX0_D1N: length 111.5
  TOP w0.114: v1(98.76,79.37) 98.58,79.2 arc(98.41,79.08) 98.21,79.04 72,79.04 arc(71.98,79.04) 71.97,79.04 69.74,79.04 arc(69.48,78.99) 69.26,78.84 arc(69.05,78.54) 68.98,78.18 68.98,71.71 arc(68.96,71.64) 68.92,71.57 68.91,71.56 arc(68.86,71.49) 68.85,71.42 J38.210 ; v1(153.57,74.62) 153.4,74.45 arc(153.23,74.34) 153.03,74.3 152.49,74.3 arc(152.42,74.31) 152.35,74.35 152.34,74.37 arc(152.27,74.41) 152.2,74.43 J23.21
  ART03 w0.102: v1(98.76,79.37) 98.92,79.21 arc(99.08,79.1) 99.27,79.06 99.67,79.06 arc(99.78,79.08) 99.87,79.14 arc(100.18,79.35) 100.55,79.42 100.78,79.42 arc(101.12,79.28) 101.26,78.94 101.26,78.91 arc(101.32,78.77) 101.46,78.71 arc(101.61,78.77) 101.66,78.91 arc(101.81,79.26) 102.15,79.4 110.03,79.4 arc(110.18,79.46) 110.24,79.6 110.24,80.16 arc(110.39,80.54) 110.77,80.69 111,80.69 arc(111.34,80.55) 111.48,80.21 111.48,80.16 arc(111.54,80.01) 111.68,79.96 111.75,79.96 arc(111.85,80) 111.89,80.09 111.89,80.21 arc(112.03,80.55) 112.37,80.69 112.73,80.69 arc(113.07,80.55) 113.21,80.21 113.21,79.52 arc(113.27,79.38) 113.41,79.32 113.73,79.32 arc(113.88,79.38) 113.94,79.52 arc(114.06,79.83) 114.37,79.96 114.47,79.96 arc(114.78,79.83) 114.9,79.52 arc(115.11,79.32) 115.31,79.52 arc(115.44,79.83) 115.74,79.96 115.84,79.96 arc(116.15,79.83) 116.27,79.52 arc(116.48,79.32) 116.68,79.52 arc(116.81,79.83) 117.11,79.96 117.21,79.96 arc(117.52,79.83) 117.65,79.52 arc(117.71,79.38) 117.85,79.32 118.8,79.32 arc(119.04,79.37) 119.24,79.5 119.93,80.19 arc(120.34,80.47) 120.84,80.56 138,80.56 arc(138.19,80.53) 138.34,80.42 139.34,79.43 arc(139.4,79.39) 139.48,79.37 139.89,79.37 arc(140.12,79.46) 140.21,79.69 140.21,80.57 arc(140.36,80.93) 140.71,81.07 140.94,81.07 arc(141.28,80.93) 141.42,80.59 141.42,79.98 arc(141.62,79.78) 141.83,79.98 141.83,80.59 arc(141.97,80.93) 142.31,81.07 147.29,81.07 arc(147.64,80.93) 147.78,80.59 147.78,79.45 arc(147.79,79.37) 147.84,79.29 148.8,78.34 arc(148.91,78.18) 148.95,77.98 148.95,74.7 arc(148.96,74.62) 149.01,74.54 149.17,74.38 arc(149.25,74.33) 149.34,74.31 153.06,74.31 arc(153.25,74.35) 153.41,74.46 v1(153.57,74.62)
MIPI_DSI_TX0_D1P: length 111.5
  TOP w0.114: v1(98.76,78.47) 98.5,78.73 arc(98.42,78.78) 98.33,78.8 72,78.8 arc(71.98,78.8) 71.97,78.8 71.97,78.8 69.74,78.8 arc(69.57,78.77) 69.43,78.67 arc(69.27,78.44) 69.22,78.18 69.22,73.04 arc(69.27,72.92) 69.4,72.87 arc(69.52,72.82) 69.57,72.69 69.57,72.59 arc(69.52,72.46) 69.4,72.41 arc(69.27,72.36) 69.22,72.24 69.22,71.63 69.35,71.5 J38.212 ; v1(153.57,73.73) 153.4,73.9 arc(153.23,74.01) 153.03,74.05 152.49,74.05 arc(152.42,74.04) 152.35,74 152.28,73.93 J23.20
  ART03 w0.102: v1(98.76,78.47) 98.92,78.63 arc(99.08,78.74) 99.27,78.78 99.67,78.78 arc(99.89,78.82) 100.07,78.95 arc(100.29,79.09) 100.55,79.14 100.78,79.14 arc(100.92,79.08) 100.98,78.94 100.98,78.91 arc(101.12,78.57) 101.46,78.43 arc(101.8,78.57) 101.94,78.91 arc(102,79.06) 102.15,79.12 110.03,79.12 arc(110.37,79.26) 110.52,79.6 110.52,80.16 arc(110.59,80.34) 110.77,80.41 111,80.41 arc(111.14,80.35) 111.2,80.21 111.2,80.16 arc(111.34,79.82) 111.68,79.68 111.75,79.68 arc(112.04,79.8) 112.16,80.09 112.16,80.21 arc(112.22,80.35) 112.37,80.41 112.73,80.41 arc(112.87,80.35) 112.93,80.21 112.93,79.52 arc(113.07,79.18) 113.41,79.04 113.73,79.04 arc(114.08,79.18) 114.22,79.52 arc(114.26,79.63) 114.37,79.68 114.47,79.68 arc(114.58,79.63) 114.62,79.52 arc(115.11,79.04) 115.59,79.52 arc(115.63,79.63) 115.74,79.68 115.84,79.68 arc(115.95,79.63) 115.99,79.52 arc(116.48,79.04) 116.96,79.52 arc(117,79.63) 117.11,79.68 117.21,79.68 arc(117.32,79.63) 117.37,79.52 arc(117.51,79.18) 117.85,79.04 118.8,79.04 arc(118.83,79.04) 118.86,79.04 118.86,79.04 arc(119.15,79.1) 119.4,79.26 119.44,79.31 120.13,79.99 arc(120.45,80.21) 120.84,80.29 138,80.29 arc(138.08,80.27) 138.15,80.23 139.14,79.23 arc(139.29,79.13) 139.48,79.09 139.89,79.09 arc(140.31,79.27) 140.49,79.69 140.49,80.57 arc(140.55,80.73) 140.71,80.79 140.94,80.79 arc(141.08,80.73) 141.14,80.59 141.14,79.98 arc(141.62,79.5) 142.11,79.98 142.11,80.59 arc(142.17,80.73) 142.31,80.79 147.29,80.79 arc(147.44,80.73) 147.5,80.59 147.5,79.45 arc(147.54,79.26) 147.65,79.1 148.6,78.14 arc(148.65,78.07) 148.67,77.98 148.67,74.7 arc(148.7,74.51) 148.81,74.35 148.98,74.18 arc(149.14,74.07) 149.34,74.04 153.06,74.04 arc(153.25,74) 153.41,73.89 v1(153.57,73.73)
MIPI_DSI_TX0_D2N: length 111.6
  TOP w0.114: J38.220 71.35,71.42 arc(71.36,71.49) 71.41,71.56 71.42,71.57 arc(71.46,71.64) 71.48,71.71 71.48,75.92 arc(71.68,76.41) 72.17,76.62 98.35,76.62 v1(98.68,76.94) ; J23.18 152.28,72.93 152.35,72.85 arc(152.42,72.81) 152.49,72.8 153.48,72.8 arc(153.81,72.66) 153.95,72.33 153.95,71.73 arc(154.18,71.51) 154.41,71.73 154.41,72.33 arc(154.55,72.66) 154.88,72.8 155.18,72.8 arc(155.39,72.84) 155.56,72.95 v1(155.73,73.12)
  ART03 w0.102: v1(98.68,76.94) 98.84,76.78 arc(99,76.67) 99.19,76.63 100.12,76.63 arc(100.75,76.76) 101.29,77.12 102.3,78.13 arc(102.69,78.39) 103.14,78.48 119.74,78.48 arc(119.88,78.54) 119.94,78.69 119.94,78.86 arc(120.06,79.17) 120.37,79.29 120.42,79.29 arc(120.76,79.15) 120.9,78.81 120.9,78.69 arc(120.96,78.54) 121.11,78.48 121.34,78.48 arc(121.48,78.54) 121.54,78.69 121.54,79.16 arc(121.68,79.51) 122.03,79.65 130.39,79.65 arc(130.73,79.51) 130.87,79.17 130.87,78.69 arc(131.07,78.48) 131.28,78.69 131.28,79.17 arc(131.76,79.65) 132.24,79.17 132.24,78.69 arc(132.45,78.48) 132.65,78.69 132.65,79.17 arc(133.13,79.65) 133.61,79.17 133.61,78.69 arc(133.82,78.48) 134.02,78.69 134.02,79.17 arc(134.5,79.65) 134.99,79.17 134.99,78.69 arc(135.19,78.48) 135.39,78.69 135.39,79.17 arc(135.53,79.51) 135.88,79.65 137.56,79.65 arc(137.75,79.61) 137.92,79.5 138.85,78.57 arc(138.92,78.52) 139.01,78.51 146.93,78.51 arc(147.34,78.43) 147.68,78.2 147.77,78.11 arc(148,77.76) 148.08,77.36 148.08,73.7 arc(148.18,73.47) 148.41,73.38 150.89,73.38 arc(151.51,73.25) 152.04,72.9 152.06,72.88 arc(152.13,72.83) 152.22,72.81 155.22,72.81 arc(155.41,72.85) 155.57,72.96 v1(155.73,73.12)
MIPI_DSI_TX0_D2P: length 111.6
  TOP w0.114: v1(155.73,72.23) 155.56,72.4 arc(155.39,72.51) 155.18,72.55 154.88,72.55 arc(154.72,72.49) 154.65,72.33 154.65,71.73 arc(154.18,71.26) 153.71,71.73 153.71,72.33 arc(153.64,72.49) 153.48,72.55 152.49,72.55 arc(152.42,72.54) 152.35,72.5 152.34,72.48 arc(152.27,72.44) 152.2,72.43 J23.17 ; v1(98.68,76.05) 98.35,76.37 82.27,76.37 arc(82.15,76.33) 82.1,76.21 arc(82.05,76.09) 81.94,76.04 81.81,76.04 arc(81.69,76.09) 81.64,76.21 arc(81.59,76.33) 81.48,76.37 72.17,76.37 arc(71.85,76.24) 71.72,75.92 71.72,71.71 arc(71.74,71.64) 71.78,71.57 71.79,71.56 arc(71.84,71.49) 71.85,71.42 J38.222
  ART03 w0.102: v1(155.73,72.23) 155.57,72.39 arc(155.41,72.5) 155.22,72.54 152.22,72.54 arc(152.02,72.57) 151.86,72.69 151.84,72.7 arc(151.4,72.99) 150.89,73.1 148.41,73.1 arc(147.98,73.27) 147.8,73.7 147.8,77.36 arc(147.74,77.66) 147.57,77.91 147.48,78 arc(147.23,78.17) 146.93,78.23 139.01,78.23 arc(138.81,78.27) 138.65,78.38 138.65,78.38 137.72,79.3 arc(137.65,79.35) 137.56,79.37 135.88,79.37 arc(135.73,79.31) 135.67,79.17 135.67,78.69 arc(135.19,78.2) 134.71,78.69 134.71,79.17 arc(134.5,79.37) 134.3,79.17 134.3,78.69 arc(133.82,78.2) 133.34,78.69 133.34,79.17 arc(133.13,79.37) 132.93,79.17 132.93,78.69 arc(132.45,78.2) 131.96,78.69 131.96,79.17 arc(131.76,79.37) 131.56,79.17 131.56,78.69 arc(131.07,78.2) 130.59,78.69 130.59,79.17 arc(130.53,79.31) 130.39,79.37 122.03,79.37 arc(121.88,79.31) 121.82,79.16 121.82,78.69 arc(121.68,78.34) 121.34,78.2 121.11,78.2 arc(120.77,78.34) 120.62,78.69 120.62,78.81 arc(120.57,78.96) 120.42,79.02 120.37,79.02 arc(120.26,78.97) 120.22,78.86 120.22,78.69 arc(120.08,78.34) 119.74,78.2 103.14,78.2 arc(102.8,78.13) 102.5,77.94 101.49,76.92 arc(100.86,76.5) 100.12,76.35 99.19,76.35 arc(99,76.32) 98.84,76.21 v1(98.68,76.05)
